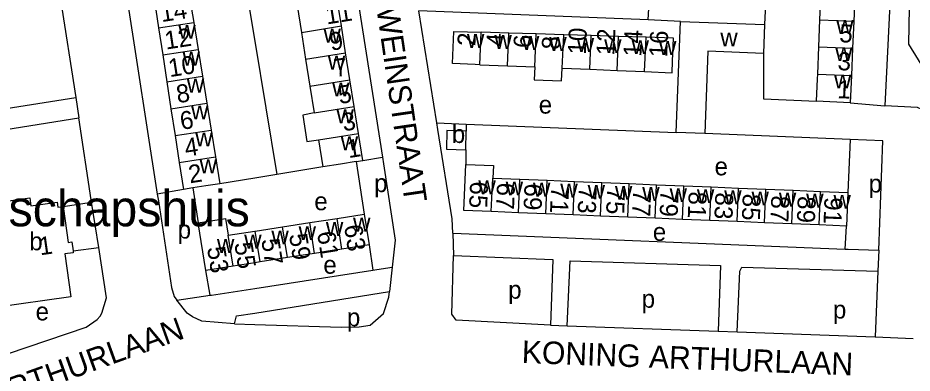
# Model space of a CAD drawing. Extents: x 159675 to 162108, y 386471 to 388472.
# Drawn here: x 160647.4 to 160845.9, y 386875.3 to 386954.2 of the extents above; entities that cross this region are included whole.
import ezdxf

# ---------------------------------------------------------------- set-up
doc = ezdxf.new("R2010")
doc.units = 0
for name, color, linetype in [('BLT_Basislijn', 7, 'Continuous'), ('BLT_Bebouwing', 7, 'Continuous'), ('BLT_Bebouwing_beschrifting', 7, 'Continuous'), ('BLT_Centroide', 7, 'Continuous'), ('BLT_Huisnummer', 7, 'Continuous'), ('BLT_Huisnummer_ tussenligend', 7, 'Continuous'), ('BLT_Onderverdeling_panden', 7, 'Continuous'), ('BLT_Straatnaam', 7, 'Continuous')]:
    doc.layers.add(name, color=color, linetype=linetype)

msp = doc.modelspace()

# ---------------------------------------------------------------- linework, layer by layer
at = {"layer": 'BLT_Basislijn'}
for p, q in [((160787.31, 386953.76), (160791.86, 387046.11)), ((160818.35, 387044.74), (160813.1, 386952.69)), ((160845.06, 387044.05), (160839.85, 386934.69)), ((160646.04, 387027.79), (160660.27, 386936.54)), ((160661.61, 387023.11), (160678.36, 386915.07)), ((160689.77, 387010.79), (160700, 386949.04)), ((160740.37, 386930.86), (160736.42, 386955.77)), ((160787.31, 386953.76), (160736.42, 386955.77)), ((160794.44, 386953.38), (160787.31, 386953.76)), ((160700, 386949.04), (160704.91, 386919.44)), ((160660.27, 386936.54), (160660.96, 386931.98)), ((160832.14, 386935.34), (160839.85, 386934.69)), ((160637.8, 386928.26), (160660.96, 386931.98)), ((160740.37, 386930.86), (160746.88, 386930.6)), ((160746.88, 386930.6), (160793.52, 386928.75)), ((160746.88, 386930.6), (160746.91, 386929.07)), ((160832.12, 386927.21), (160799.85, 386928.51)), ((160832.12, 386927.21), (160831.6, 386915.42)), ((160746.81, 386924.92), (160746.84, 386921.65)), ((160722.46, 386922.29), (160724.29, 386910.59)), ((160723.97, 386922.52), (160728.37, 386923.23)), ((160715.11, 386921.12), (160704.91, 386919.44)), ((160700, 386918.63), (160692.23, 386917.35)), ((160704.91, 386919.44), (160700, 386918.63)), ((160684.14, 386916.08), (160678.36, 386915.07)), ((160686.27, 386916.42), (160687.44, 386908.7)), ((160657.48, 386912.29), (160663.76, 386913.27)), ((160831.04, 386902.86), (160831.3, 386907.96)), ((160743.95, 386906.41), (160744.11, 386901.41)), ((160743.95, 386906.41), (160831.04, 386902.86)), ((160725.36, 386903.81), (160726.19, 386898.17)), ((160659.66, 386902.43), (160665.4, 386903.23)), ((160838.46, 386902.62), (160838.25, 386897.94)), ((160690.1, 386892.6), (160689.12, 386898.08)), ((160700, 386894.12), (160726.19, 386898.17)), ((160730.49, 386898.82), (160729.87, 386893.42)), ((160838.25, 386897.94), (160837.68, 386883.33)), ((160682.69, 386891.5), (160690.1, 386892.6)), ((160700, 386888.64), (160729.87, 386893.42)), ((160695.49, 386886.28), (160700, 386886.13)), ((160765.65, 386885.96), (160769.32, 386885.82)), ((160769.32, 386885.82), (160802.83, 386884.6)), ((160802.83, 386884.6), (160807.08, 386884.45)), ((160807.08, 386884.45), (160837.68, 386883.33)), ((160837.68, 386883.33), (160846.11, 386883.02))]:
    msp.add_line(p, q, dxfattribs=at)
for points in [[(160579.33, 387044.54), (160541.58, 387038.36), (160542.39, 387030.6), (160553.88, 386962.03), (160560.43, 386920.74), (160660.27, 386936.54)], [(160777.73, 387033.76), (160777.31, 387024.94), (160729.84, 387017.06), (160714, 387014.74), (160728.37, 386923.23)], [(160860.44, 386970.92), (160845.97, 386971.28), (160845.81, 386971.07), (160845.29, 386960.51), (160845.09, 386948.32), (160864.77, 386916.45), (160865.08, 386915.53)], [(160812.86, 386946.3), (160812.91, 386936.19), (160824.69, 386935.67)], [(160848, 386933.83), (160847.04, 386934.3), (160839.85, 386934.69)], [(160663.76, 386913.27), (160663.67, 386913.81), (160660.96, 386931.98)], [(160743.95, 386906.41), (160743.79, 386909.6), (160740.6, 386929.43), (160740.37, 386930.86)], [(160838.46, 386902.62), (160839.39, 386926.91), (160832.12, 386927.21)], [(160728.37, 386923.23), (160728.59, 386921.8), (160731.17, 386904.86), (160730.49, 386898.82)], [(160678.36, 386915.07), (160678.59, 386913.59), (160681.51, 386894.29), (160682.11, 386892.3), (160682.69, 386891.5)], [(160665.4, 386903.23), (160663.76, 386913.27)], [(160643.91, 386879.19), (160645.32, 386879.67), (160662.54, 386885.53), (160665.02, 386887.2), (160665.65, 386887.94), (160666.08, 386888.6), (160667.09, 386892.03), (160665.4, 386903.23)], [(160831.04, 386902.86), (160831.71, 386902.83), (160838.46, 386902.62)], [(160765.65, 386885.96), (160744.7, 386887.09), (160743.69, 386888.36), (160744.11, 386901.41)], [(160744.11, 386901.41), (160766.17, 386900.52), (160765.65, 386885.96)], [(160769.32, 386885.82), (160769.97, 386900.23), (160803.36, 386899.19), (160802.83, 386884.6)], [(160726.19, 386898.17), (160727.11, 386898.31), (160730.49, 386898.82)], [(160807.08, 386884.45), (160807.63, 386897.97), (160808.11, 386898.84), (160838.25, 386897.94)], [(160690.1, 386892.6), (160690.38, 386892.64), (160700, 386894.12)], [(160700, 386886.13), (160719.15, 386885.48), (160723.13, 386885.57), (160725.6, 386885.97), (160728.55, 386888.52), (160729.76, 386892.15), (160729.87, 386893.42)], [(160695.49, 386886.28), (160688.24, 386886.85), (160686.17, 386887.77), (160685.01, 386888.65), (160682.69, 386891.5)], [(160695.49, 386886.28), (160695.97, 386888), (160700, 386888.64)]]:
    msp.add_lwpolyline(points, dxfattribs=at)
at = {"layer": 'BLT_Bebouwing'}
for p, q in [((160825.41, 386953.79), (160825.65, 386959.82)), ((160833.19, 386959.53), (160832.93, 386953.49)), ((160677.74, 386957.95), (160678.65, 386951.97)), ((160685.47, 386959.13), (160686.44, 386953.16)), ((160719.21, 386952.4), (160718.26, 386958.37)), ((160709.37, 386956.95), (160710.33, 386950.98)), ((160825.17, 386947.76), (160825.41, 386953.79)), ((160832.93, 386953.49), (160832.67, 386947.46)), ((160678.65, 386951.97), (160679.57, 386945.99)), ((160686.44, 386953.16), (160687.4, 386947.19)), ((160720.16, 386946.43), (160719.21, 386952.4)), ((160793.52, 386928.75), (160794.44, 386953.38)), ((160794.44, 386953.38), (160813.1, 386952.69)), ((160813.1, 386952.69), (160812.86, 386946.3)), ((160710.33, 386950.98), (160711.28, 386945.01)), ((160756.37, 386950.82), (160750.27, 386951.01)), ((160762.46, 386950.64), (160756.37, 386950.82)), ((160768.55, 386950.45), (160762.46, 386950.64)), ((160774.64, 386950.26), (160768.55, 386950.45)), ((160780.73, 386950.07), (160774.64, 386950.26)), ((160786.83, 386949.88), (160780.73, 386950.07)), ((160824.93, 386941.72), (160825.17, 386947.76)), ((160832.67, 386947.46), (160832.41, 386941.43)), ((160679.57, 386945.99), (160680.48, 386940.01)), ((160687.4, 386947.19), (160688.37, 386941.22)), ((160721.11, 386940.45), (160720.16, 386946.43)), ((160711.28, 386945.01), (160712.24, 386939.04)), ((160749.97, 386943.8), (160756.06, 386943.55)), ((160756.06, 386943.55), (160762.15, 386943.29)), ((160768.24, 386943.03), (160774.33, 386942.77)), ((160774.33, 386942.77), (160780.42, 386942.52)), ((160780.42, 386942.52), (160786.5, 386942.26)), ((160680.48, 386940.01), (160681.39, 386934.03)), ((160688.37, 386941.22), (160689.34, 386935.24)), ((160722.06, 386934.48), (160721.11, 386940.45)), ((160832.41, 386941.43), (160832.14, 386935.34)), ((160712.24, 386939.04), (160713.19, 386933.07)), ((160832.14, 386935.34), (160824.69, 386935.67)), ((160681.39, 386934.03), (160682.31, 386928.05)), ((160689.34, 386935.24), (160690.3, 386929.27)), ((160723.01, 386928.51), (160722.06, 386934.48)), ((160682.31, 386928.05), (160683.22, 386922.07)), ((160690.3, 386929.27), (160691.27, 386923.3)), ((160723.97, 386922.52), (160723.01, 386928.51)), ((160746.81, 386924.92), (160746.91, 386929.07)), ((160799.85, 386928.51), (160793.52, 386928.75)), ((160714.15, 386927.1), (160715.11, 386921.12)), ((160683.22, 386922.07), (160684.14, 386916.08)), ((160691.27, 386923.3), (160692.23, 386917.35)), ((160722.46, 386922.29), (160723.97, 386922.52)), ((160752.79, 386918.62), (160758.85, 386918.38)), ((160758.85, 386918.38), (160764.91, 386918.13)), ((160764.91, 386918.13), (160770.98, 386917.88)), ((160770.98, 386917.88), (160777.04, 386917.64)), ((160686.27, 386916.42), (160684.14, 386916.08)), ((160777.04, 386917.64), (160783.1, 386917.39)), ((160783.1, 386917.39), (160789.16, 386917.15)), ((160789.16, 386917.15), (160795.23, 386916.9)), ((160795.23, 386916.9), (160801.29, 386916.65)), ((160801.29, 386916.65), (160807.35, 386916.41)), ((160807.35, 386916.41), (160813.42, 386916.16)), ((160813.42, 386916.16), (160819.48, 386915.91)), ((160819.48, 386915.91), (160825.54, 386915.67)), ((160825.54, 386915.67), (160831.6, 386915.42)), ((160831.6, 386915.42), (160831.3, 386907.96)), ((160718.25, 386909.66), (160724.29, 386910.59)), ((160724.29, 386910.59), (160725.36, 386903.81)), ((160758.55, 386910.92), (160752.48, 386911.16)), ((160764.61, 386910.67), (160758.55, 386910.92)), ((160770.67, 386910.42), (160764.61, 386910.67)), ((160776.74, 386910.18), (160770.67, 386910.42)), ((160782.8, 386909.93), (160776.74, 386910.18)), ((160788.86, 386909.68), (160782.8, 386909.93)), ((160689.12, 386898.08), (160687.44, 386908.7)), ((160700.11, 386906.86), (160706.16, 386907.79)), ((160706.16, 386907.79), (160712.2, 386908.73)), ((160712.2, 386908.73), (160718.25, 386909.66)), ((160794.92, 386909.44), (160788.86, 386909.68)), ((160800.99, 386909.19), (160794.92, 386909.44)), ((160807.05, 386908.95), (160800.99, 386909.19)), ((160813.11, 386908.7), (160807.05, 386908.95)), ((160819.18, 386908.45), (160813.11, 386908.7)), ((160825.24, 386908.21), (160819.18, 386908.45)), ((160831.3, 386907.96), (160825.24, 386908.21)), ((160694.07, 386905.93), (160700, 386906.84)), ((160700, 386906.84), (160700.11, 386906.86)), ((160725.36, 386903.81), (160719.32, 386902.86)), ((160713.28, 386901.9), (160707.24, 386900.95)), ((160719.32, 386902.86), (160713.28, 386901.9)), ((160701.2, 386899.99), (160700, 386899.8)), ((160707.24, 386900.95), (160701.2, 386899.99)), ((160695.16, 386899.03), (160689.12, 386898.08)), ((160700, 386899.8), (160695.16, 386899.03))]:
    msp.add_line(p, q, dxfattribs=at)
for points in [[(160749.97, 386943.8), (160748.88, 386943.85), (160743.88, 386944.06), (160744.16, 386951.2), (160750.27, 386951.01)], [(160786.5, 386942.26), (160792.59, 386942), (160792.69, 386944.55), (160792.89, 386949.69), (160786.83, 386949.88)], [(160812.86, 386946.3), (160800.54, 386946.77), (160799.85, 386928.51)], [(160762.15, 386943.29), (160761.96, 386940.43), (160768.04, 386940.18), (160768.24, 386943.03)], [(160824.69, 386935.67), (160824.89, 386940.67), (160824.93, 386941.72)], [(160713.19, 386933.07), (160710.63, 386932.59), (160711.57, 386926.71), (160714.15, 386927.1)], [(160746.91, 386929.07), (160742.61, 386929.17), (160742.51, 386925.02), (160746.81, 386924.92)], [(160722.46, 386922.29), (160719.03, 386921.74), (160715.11, 386921.12)], [(160752.48, 386911.16), (160746.42, 386911.41), (160746.84, 386921.65)], [(160746.84, 386921.65), (160753, 386921.4), (160752.79, 386918.62)], [(160692.23, 386917.35), (160689.12, 386916.86), (160686.27, 386916.42)], [(160640.15, 386912.84), (160650.08, 386914.23), (160650.32, 386912.46), (160656.1, 386913.26), (160656.26, 386912.12), (160657.48, 386912.29)], [(160657.48, 386912.29), (160658.3, 386906.43), (160658.59, 386904.32), (160659.38, 386904.43), (160659.66, 386902.43)], [(160687.44, 386908.7), (160693.46, 386909.63), (160694.07, 386905.93)], [(160659.66, 386902.43), (160659.72, 386902.05), (160657.82, 386901.78), (160659.16, 386892.21), (160642.29, 386889.86)]]:
    msp.add_lwpolyline(points, dxfattribs=at)
at = {"layer": 'BLT_Onderverdeling_panden'}
for p, q in [((160825.41, 386953.79), (160832.93, 386953.49)), ((160678.65, 386951.97), (160686.44, 386953.16)), ((160710.33, 386950.98), (160719.21, 386952.4)), ((160749.97, 386943.8), (160750.27, 386951.01)), ((160756.06, 386943.55), (160756.37, 386950.82)), ((160762.15, 386943.29), (160762.46, 386950.64)), ((160768.24, 386943.03), (160768.55, 386950.45)), ((160774.33, 386942.77), (160774.64, 386950.26)), ((160780.42, 386942.52), (160780.73, 386950.07)), ((160786.5, 386942.26), (160786.83, 386949.88)), ((160825.17, 386947.76), (160832.67, 386947.46)), ((160679.57, 386945.99), (160687.4, 386947.19)), ((160711.28, 386945.01), (160720.16, 386946.43)), ((160824.93, 386941.72), (160832.41, 386941.43)), ((160680.48, 386940.01), (160688.37, 386941.22)), ((160712.24, 386939.04), (160721.11, 386940.45)), ((160681.39, 386934.03), (160689.34, 386935.24)), ((160713.19, 386933.07), (160722.06, 386934.48)), ((160682.31, 386928.05), (160690.3, 386929.27)), ((160714.15, 386927.1), (160723.01, 386928.51)), ((160683.22, 386922.07), (160691.27, 386923.3)), ((160752.48, 386911.16), (160752.79, 386918.62)), ((160758.55, 386910.92), (160758.85, 386918.38)), ((160764.61, 386910.67), (160764.91, 386918.13)), ((160770.67, 386910.42), (160770.98, 386917.88)), ((160776.74, 386910.18), (160777.04, 386917.64)), ((160782.8, 386909.93), (160783.1, 386917.39)), ((160788.86, 386909.68), (160789.16, 386917.15)), ((160794.92, 386909.44), (160795.23, 386916.9)), ((160800.99, 386909.19), (160801.29, 386916.65)), ((160807.05, 386908.95), (160807.35, 386916.41)), ((160813.11, 386908.7), (160813.42, 386916.16)), ((160819.18, 386908.45), (160819.48, 386915.91)), ((160825.24, 386908.21), (160825.54, 386915.67)), ((160707.24, 386900.95), (160706.16, 386907.79)), ((160713.28, 386901.9), (160712.2, 386908.73)), ((160719.32, 386902.86), (160718.25, 386909.66)), ((160695.16, 386899.03), (160694.07, 386905.93)), ((160701.2, 386899.99), (160700.11, 386906.86))]:
    msp.add_line(p, q, dxfattribs=at)

# ---------------------------------------------------------------- texts
at = {"layer": 'BLT_Bebouwing_beschrifting'}
msp.add_text('Gemeenschapshuis', height=8, dxfattribs=at).set_placement((160604.33, 386907.91))
at = {"layer": 'BLT_Centroide'}
for s, p in [('w', (160829.04, 386950.62)), ('w', (160683.02, 386949.56)), ('w', (160715.24, 386948.72)), ('w', (160747.08, 386947.53)), ('w', (160753.17, 386947.3)), ('w', (160759.27, 386947.08)), ('w', (160765.34, 386946.84)), ('w', (160771.44, 386946.62)), ('w', (160777.53, 386946.39)), ('w', (160803.31, 386947.86)), ('w', (160783.62, 386946.17)), ('w', (160789.7, 386945.95)), ('w', (160828.8, 386944.59)), ('w', (160683.96, 386943.59)), ('w', (160716.2, 386942.72)), ('w', (160828.54, 386938.53)), ('w', (160684.9, 386937.62)), ('w', (160717.16, 386936.75)), ('e', (160763.01, 386932.93)), ('w', (160685.84, 386931.66)), ('w', (160718.11, 386930.78)), ('b', (160743.72, 386926.41)), ('w', (160686.78, 386925.66)), ('w', (160719.06, 386924.81)), ('w', (160687.73, 386919.69)), ('e', (160802.03, 386919.22)), ('p', (160726.48, 386915.51)), ('w', (160749.61, 386915.02)), ('w', (160755.67, 386914.77)), ('p', (160836.22, 386915.4)), ('w', (160761.73, 386914.52)), ('w', (160767.8, 386914.27)), ('w', (160773.86, 386914.03)), ('w', (160779.92, 386913.8)), ('w', (160785.98, 386913.55)), ('w', (160792.05, 386913.3)), ('w', (160798.11, 386913.05)), ('w', (160804.17, 386912.8)), ('e', (160713.2, 386911.48)), ('w', (160810.23, 386912.55)), ('w', (160816.3, 386912.3)), ('w', (160822.36, 386912.05)), ('w', (160828.42, 386911.81)), ('w', (160721.8, 386906.73)), ('p', (160682.88, 386905.18)), ('w', (160709.72, 386904.84)), ('w', (160715.77, 386905.78)), ('e', (160788.33, 386904.68)), ('b', (160649.94, 386902.58)), ('w', (160697.64, 386902.95)), ('w', (160703.67, 386903.89)), ('w', (160691.59, 386902)), ('e', (160715.21, 386897.38)), ('p', (160756.23, 386891.83)), ('p', (160785.86, 386889.82)), ('e', (160651.35, 386887.01)), ('p', (160828.3, 386887.42)), ('p', (160720.44, 386885.7))]:
    msp.add_text(s, height=4, dxfattribs=at).set_placement(p)
at = {"layer": 'BLT_Huisnummer'}
for s, rotation, p in [('14', 8.9273, (160679.31, 386953.24)), ('10', 87.5764, (160773.46, 386945.99)), ('5', 357.426, (160829.64, 386948.8)), ('9', 8.9988, (160716.91, 386946.89)), ('2', 87.5764, (160748.94, 386947.86)), ('6', 87.5764, (160761.39, 386947.43)), ('16', 87.5764, (160791.5, 386945.36)), ('10', 8.9273, (160681.12, 386941.02)), ('1', 357.426, (160829.2, 386936.38)), ('5', 8.9988, (160718.8, 386935.05)), ('6', 8.9273, (160683.71, 386929.3)), ('1', 8.9988, (160720.81, 386923.04)), ('2', 8.9273, (160685.59, 386917.44)), ('65', 267.6741, (160747.8, 386917.94)), ('69', 267.6741, (160759.87, 386917.48)), ('73', 267.6741, (160771.9, 386916.74)), ('77', 267.6741, (160783.98, 386916.1)), ('81', 267.6741, (160796.32, 386915.69)), ('85', 267.6741, (160808.32, 386915.2)), ('91', 267.6741, (160826.45, 386914.44)), ('63', 278.9956, (160719.79, 386908)), ('1', 7.9489, (160652.37, 386901.46)), ('57', 278.9956, (160701.42, 386904.92)), ('53', 278.9956, (160689.4, 386903.15))]:
    msp.add_text(s, height=4, rotation=rotation, dxfattribs=at).set_placement(p)
at = {"layer": 'BLT_Huisnummer_ tussenligend'}
for s, rotation, p in [('11', 9.0683, (160715.97, 386952.72)), ('12', 8.6921, (160680.29, 386947.15)), ('12', 87.5764, (160779.78, 386945.79)), ('4', 87.5764, (160755.37, 386947.76)), ('8', 87.5764, (160767.66, 386947.08)), ('14', 87.5764, (160785.78, 386945.5)), ('3', 357.7385, (160829.28, 386942.6)), ('7', 9.0683, (160717.9, 386941.01)), ('8', 8.6921, (160682.88, 386935.24)), ('3', 9.0683, (160719.69, 386928.99)), ('4', 8.6921, (160684.71, 386923.35)), ('67', 267.6741, (160753.76, 386917.68)), ('71', 267.6741, (160765.75, 386916.81)), ('75', 267.6741, (160778.2, 386916.57)), ('79', 267.6741, (160790.07, 386916.03)), ('83', 267.6741, (160802.23, 386915.48)), ('87', 267.6741, (160814.65, 386914.81)), ('89', 267.6741, (160820.52, 386914.67)), ('59', 278.9859, (160707.59, 386906.03)), ('61', 278.9859, (160713.8, 386906.53)), ('55', 278.9859, (160695.44, 386904.11))]:
    msp.add_text(s, height=4, rotation=rotation, dxfattribs=at).set_placement(p)
at = {"layer": 'BLT_Straatnaam'}
for s, height, rotation, p in [('WALEWEINSTRAAT', 5, 278.2824, (160724.25, 386975.05)), ('KONING ARTHURLAAN', 5, 19.8279, (160615.5, 386858.17)), ('KONING ARTHURLAAN', 4.9999, 357.828, (160759.18, 386877.58))]:
    msp.add_text(s, height=height, rotation=rotation, dxfattribs=at).set_placement(p)

doc.saveas('drawing.dxf')
